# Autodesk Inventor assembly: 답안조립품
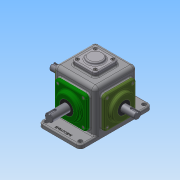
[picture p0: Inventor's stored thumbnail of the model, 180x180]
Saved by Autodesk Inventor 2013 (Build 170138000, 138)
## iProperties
Created: 2018-09
Part Number: 답안조립품
Document SubType Name: Assembly
Designer: Administrator
Mass: 3064.44 g
Surface Area: 2604.28 cm^2
Volume: 801.794 cm^3
Density: 3.82198 g/cm^3
Author: Administrator
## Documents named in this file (15)
- C:\Users\Administrator\Desktop\380908V1009\답안조립품.iam
- C:\Users\Administrator\Desktop\380908V1009\본체.ipt
- C:\Users\Administrator\Desktop\380908V1009\서브축.ipt
- C:\Users\Administrator\Desktop\380908V1009\서브베벨기어.ipt
- C:\Users\Administrator\Desktop\380908V1009\키 4x4.ipt
- C:\Users\Administrator\Desktop\380908V1009\베어링 6203.ipt
- C:\Users\Administrator\Desktop\380908V1009\서브커버.ipt
- C:\Users\Administrator\Desktop\380908V1009\오일 실 17 32 8.ipt
- C:\Users\Administrator\Desktop\380908V1009\볼트 M4.ipt
- C:\Users\Administrator\Desktop\380908V1009\상부커버.ipt
- C:\Users\Administrator\Desktop\380908V1009\메인축.ipt
- C:\Users\Administrator\Desktop\380908V1009\메인베벨기어.ipt
- C:\Users\Administrator\Desktop\380908V1009\베어링 6204.ipt
- C:\Users\Administrator\Desktop\380908V1009\메인커버.ipt
- C:\Users\Administrator\Desktop\380908V1009\오일 실 20 35 8.ipt
